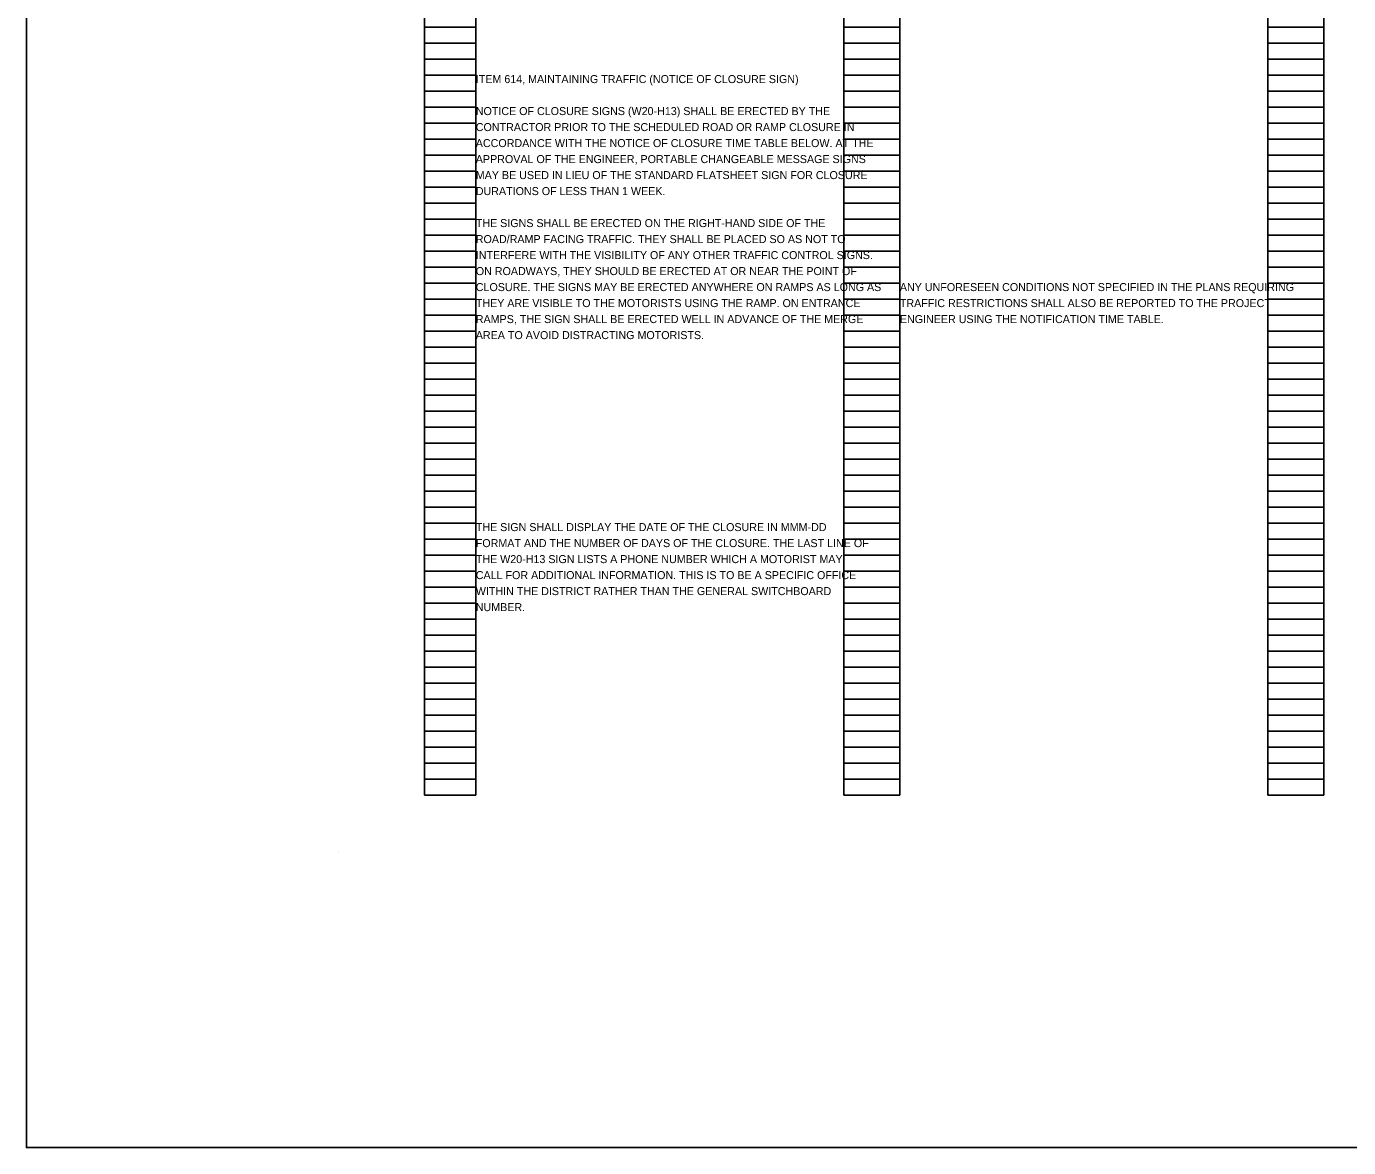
# Model space of a CAD drawing. Extents: x -49 to 78, y -12 to 34.
# Drawn here: x -49.1 to -25.97, y -7.38 to 12.24 of the extents above; entities that cross this region are included whole.
import ezdxf

# ---------------------------------------------------------------- set-up
doc = ezdxf.new("R2010")
doc.units = 0
for name, color, linetype in [('SC_Scratch1', 7, 'Continuous'), ('SH_Data', 7, 'Continuous'), ('SH_Text', 7, 'Continuous')]:
    doc.layers.add(name, color=color, linetype=linetype)

msp = doc.modelspace()

# ---------------------------------------------------------------- linework, layer by layer
at = {"layer": 'SC_Scratch1'}
msp.add_lwpolyline([(-49.098, 23.346), (-6.056, 23.346), (-6.056, -7.377), (-49.098, -7.377)], close=True, dxfattribs=at)
at = {"layer": 'SH_Data'}
for p, q in [((-42.136, -1.21), (-42.136, 18.95)), ((-41.236, -1.21), (-41.236, 18.95)), ((-34.796, -1.21), (-34.796, 18.95)), ((-33.816, -1.21), (-33.816, 18.95)), ((-27.376, -1.21), (-27.376, 18.95)), ((-26.396, -1.21), (-26.396, 18.95)), ((-42.136, 12.23), (-41.236, 12.23)), ((-34.796, 12.23), (-33.816, 12.23)), ((-27.376, 12.23), (-26.396, 12.23)), ((-42.136, 11.95), (-41.236, 11.95)), ((-34.796, 11.95), (-33.816, 11.95)), ((-27.376, 11.95), (-26.396, 11.95)), ((-42.136, 11.67), (-41.236, 11.67)), ((-34.796, 11.67), (-33.816, 11.67)), ((-27.376, 11.67), (-26.396, 11.67)), ((-42.136, 11.39), (-41.236, 11.39)), ((-34.796, 11.39), (-33.816, 11.39)), ((-27.376, 11.39), (-26.396, 11.39)), ((-42.136, 11.11), (-41.236, 11.11)), ((-34.796, 11.11), (-33.816, 11.11)), ((-27.376, 11.11), (-26.396, 11.11)), ((-42.136, 10.83), (-41.236, 10.83)), ((-34.796, 10.83), (-33.816, 10.83)), ((-27.376, 10.83), (-26.396, 10.83)), ((-42.136, 10.55), (-41.236, 10.55)), ((-34.796, 10.55), (-33.816, 10.55)), ((-27.376, 10.55), (-26.396, 10.55)), ((-42.136, 10.27), (-41.236, 10.27)), ((-34.796, 10.27), (-33.816, 10.27)), ((-27.376, 10.27), (-26.396, 10.27)), ((-42.136, 9.99), (-41.236, 9.99)), ((-34.796, 9.99), (-33.816, 9.99)), ((-27.376, 9.99), (-26.396, 9.99)), ((-42.136, 9.71), (-41.236, 9.71)), ((-34.796, 9.71), (-33.816, 9.71)), ((-27.376, 9.71), (-26.396, 9.71)), ((-42.136, 9.43), (-41.236, 9.43)), ((-34.796, 9.43), (-33.816, 9.43)), ((-27.376, 9.43), (-26.396, 9.43)), ((-42.136, 9.15), (-41.236, 9.15)), ((-34.796, 9.15), (-33.816, 9.15)), ((-27.376, 9.15), (-26.396, 9.15)), ((-42.136, 8.87), (-41.236, 8.87)), ((-34.796, 8.87), (-33.816, 8.87)), ((-27.376, 8.87), (-26.396, 8.87)), ((-42.136, 8.59), (-41.236, 8.59)), ((-34.796, 8.59), (-33.816, 8.59)), ((-27.376, 8.59), (-26.396, 8.59)), ((-42.136, 8.31), (-41.236, 8.31)), ((-34.796, 8.31), (-33.816, 8.31)), ((-27.376, 8.31), (-26.396, 8.31)), ((-42.136, 8.03), (-41.236, 8.03)), ((-34.796, 8.03), (-33.816, 8.03)), ((-27.376, 8.03), (-26.396, 8.03)), ((-42.136, 7.75), (-41.236, 7.75)), ((-34.796, 7.75), (-33.816, 7.75)), ((-27.376, 7.75), (-26.396, 7.75)), ((-42.136, 7.47), (-41.236, 7.47)), ((-34.796, 7.47), (-33.816, 7.47)), ((-27.376, 7.47), (-26.396, 7.47)), ((-42.136, 7.19), (-41.236, 7.19)), ((-34.796, 7.19), (-33.816, 7.19)), ((-27.376, 7.19), (-26.396, 7.19)), ((-42.136, 6.91), (-41.236, 6.91)), ((-34.796, 6.91), (-33.816, 6.91)), ((-27.376, 6.91), (-26.396, 6.91)), ((-42.136, 6.63), (-41.236, 6.63)), ((-34.796, 6.63), (-33.816, 6.63)), ((-27.376, 6.63), (-26.396, 6.63)), ((-42.136, 6.35), (-41.236, 6.35)), ((-34.796, 6.35), (-33.816, 6.35)), ((-27.376, 6.35), (-26.396, 6.35)), ((-42.136, 6.07), (-41.236, 6.07)), ((-34.796, 6.07), (-33.816, 6.07)), ((-27.376, 6.07), (-26.396, 6.07)), ((-42.136, 5.79), (-41.236, 5.79)), ((-34.796, 5.79), (-33.816, 5.79)), ((-27.376, 5.79), (-26.396, 5.79)), ((-42.136, 5.51), (-41.236, 5.51)), ((-34.796, 5.51), (-33.816, 5.51)), ((-27.376, 5.51), (-26.396, 5.51)), ((-42.136, 5.23), (-41.236, 5.23)), ((-34.796, 5.23), (-33.816, 5.23)), ((-27.376, 5.23), (-26.396, 5.23)), ((-42.136, 4.95), (-41.236, 4.95)), ((-34.796, 4.95), (-33.816, 4.95)), ((-27.376, 4.95), (-26.396, 4.95)), ((-42.136, 4.67), (-41.236, 4.67)), ((-34.796, 4.67), (-33.816, 4.67)), ((-27.376, 4.67), (-26.396, 4.67)), ((-42.136, 4.39), (-41.236, 4.39)), ((-34.796, 4.39), (-33.816, 4.39)), ((-27.376, 4.39), (-26.396, 4.39)), ((-42.136, 4.11), (-41.236, 4.11)), ((-34.796, 4.11), (-33.816, 4.11)), ((-27.376, 4.11), (-26.396, 4.11)), ((-42.136, 3.83), (-41.236, 3.83)), ((-34.796, 3.83), (-33.816, 3.83)), ((-27.376, 3.83), (-26.396, 3.83)), ((-42.136, 3.55), (-41.236, 3.55)), ((-34.796, 3.55), (-33.816, 3.55)), ((-27.376, 3.55), (-26.396, 3.55)), ((-42.136, 3.27), (-41.236, 3.27)), ((-34.796, 3.27), (-33.816, 3.27)), ((-27.376, 3.27), (-26.396, 3.27)), ((-42.136, 2.99), (-41.236, 2.99)), ((-34.796, 2.99), (-33.816, 2.99)), ((-27.376, 2.99), (-26.396, 2.99)), ((-42.136, 2.71), (-41.236, 2.71)), ((-34.796, 2.71), (-33.816, 2.71)), ((-27.376, 2.71), (-26.396, 2.71)), ((-42.136, 2.43), (-41.236, 2.43)), ((-34.796, 2.43), (-33.816, 2.43)), ((-27.376, 2.43), (-26.396, 2.43)), ((-42.136, 2.15), (-41.236, 2.15)), ((-34.796, 2.15), (-33.816, 2.15)), ((-27.376, 2.15), (-26.396, 2.15)), ((-42.136, 1.87), (-41.236, 1.87)), ((-34.796, 1.87), (-33.816, 1.87)), ((-27.376, 1.87), (-26.396, 1.87)), ((-42.136, 1.59), (-41.236, 1.59)), ((-34.796, 1.59), (-33.816, 1.59)), ((-27.376, 1.59), (-26.396, 1.59)), ((-42.136, 1.31), (-41.236, 1.31)), ((-34.796, 1.31), (-33.816, 1.31)), ((-27.376, 1.31), (-26.396, 1.31)), ((-42.136, 1.03), (-41.236, 1.03)), ((-34.796, 1.03), (-33.816, 1.03)), ((-27.376, 1.03), (-26.396, 1.03)), ((-42.136, 0.75), (-41.236, 0.75)), ((-34.796, 0.75), (-33.816, 0.75)), ((-27.376, 0.75), (-26.396, 0.75)), ((-42.136, 0.47), (-41.236, 0.47)), ((-34.796, 0.47), (-33.816, 0.47)), ((-27.376, 0.47), (-26.396, 0.47)), ((-42.136, 0.19), (-41.236, 0.19)), ((-34.796, 0.19), (-33.816, 0.19)), ((-27.376, 0.19), (-26.396, 0.19)), ((-42.136, -0.09), (-41.236, -0.09)), ((-34.796, -0.09), (-33.816, -0.09)), ((-27.376, -0.09), (-26.396, -0.09)), ((-42.136, -0.37), (-41.236, -0.37)), ((-34.796, -0.37), (-33.816, -0.37)), ((-27.376, -0.37), (-26.396, -0.37)), ((-42.136, -0.65), (-41.236, -0.65)), ((-34.796, -0.65), (-33.816, -0.65)), ((-27.376, -0.65), (-26.396, -0.65)), ((-42.136, -0.93), (-41.236, -0.93)), ((-34.796, -0.93), (-33.816, -0.93)), ((-27.376, -0.93), (-26.396, -0.93)), ((-42.136, -1.21), (-41.236, -1.21)), ((-34.796, -1.21), (-33.816, -1.21)), ((-27.376, -1.21), (-26.396, -1.21)), ((-43.636, -2.19), (-43.636, -2.19))]:
    msp.add_line(p, q, dxfattribs=at)

# ---------------------------------------------------------------- texts
at = {"layer": 'SH_Text'}
for s, p in [('ITEM 614, MAINTAINING TRAFFIC (NOTICE OF CLOSURE SIGN)', (-41.236, 11.25)), ('NOTICE OF CLOSURE SIGNS (W20-H13) SHALL BE ERECTED BY THE ', (-41.236, 10.69)), ('CONTRACTOR PRIOR TO THE SCHEDULED ROAD OR RAMP CLOSURE IN ', (-41.236, 10.41)), ('ACCORDANCE WITH THE NOTICE OF CLOSURE TIME TABLE BELOW. AT THE ', (-41.236, 10.13)), ('APPROVAL OF THE ENGINEER, PORTABLE CHANGEABLE MESSAGE SIGNS ', (-41.236, 9.85)), ('MAY BE USED IN LIEU OF THE STANDARD FLATSHEET SIGN FOR CLOSURE ', (-41.236, 9.57)), ('DURATIONS OF LESS THAN 1 WEEK.', (-41.236, 9.29)), ('THE SIGNS SHALL BE ERECTED ON THE RIGHT-HAND SIDE OF THE ', (-41.236, 8.73)), ('ROAD/RAMP FACING TRAFFIC. THEY SHALL BE PLACED SO AS NOT TO ', (-41.236, 8.45)), ('INTERFERE WITH THE VISIBILITY OF ANY OTHER TRAFFIC CONTROL SIGNS. ', (-41.236, 8.17)), ('ON ROADWAYS, THEY SHOULD BE ERECTED AT OR NEAR THE POINT OF ', (-41.236, 7.89)), ('CLOSURE. THE SIGNS MAY BE ERECTED ANYWHERE ON RAMPS AS LONG AS ', (-41.236, 7.61)), ('ANY UNFORESEEN CONDITIONS NOT SPECIFIED IN THE PLANS REQUIRING ', (-33.816, 7.61)), ('THEY ARE VISIBLE TO THE MOTORISTS USING THE RAMP. ON ENTRANCE ', (-41.236, 7.33)), ('TRAFFIC RESTRICTIONS SHALL ALSO BE REPORTED TO THE PROJECT ', (-33.816, 7.33)), ('RAMPS, THE SIGN SHALL BE ERECTED WELL IN ADVANCE OF THE MERGE ', (-41.236, 7.05)), ('ENGINEER USING THE NOTIFICATION TIME TABLE.', (-33.816, 7.05)), ('AREA TO AVOID DISTRACTING MOTORISTS. ', (-41.236, 6.77)), ('THE SIGN SHALL DISPLAY THE DATE OF THE CLOSURE IN MMM-DD ', (-41.236, 3.41)), ('FORMAT AND THE NUMBER OF DAYS OF THE CLOSURE. THE LAST LINE OF ', (-41.236, 3.13)), ('THE W20-H13 SIGN LISTS A PHONE NUMBER WHICH A MOTORIST MAY ', (-41.236, 2.85)), ('CALL FOR ADDITIONAL INFORMATION. THIS IS TO BE A SPECIFIC OFFICE ', (-41.236, 2.57)), ('WITHIN THE DISTRICT RATHER THAN THE GENERAL SWITCHBOARD ', (-41.236, 2.29)), ('NUMBER.', (-41.236, 2.01))]:
    msp.add_text(s, height=0.14, dxfattribs=at).set_placement(p)

doc.saveas('drawing.dxf')
